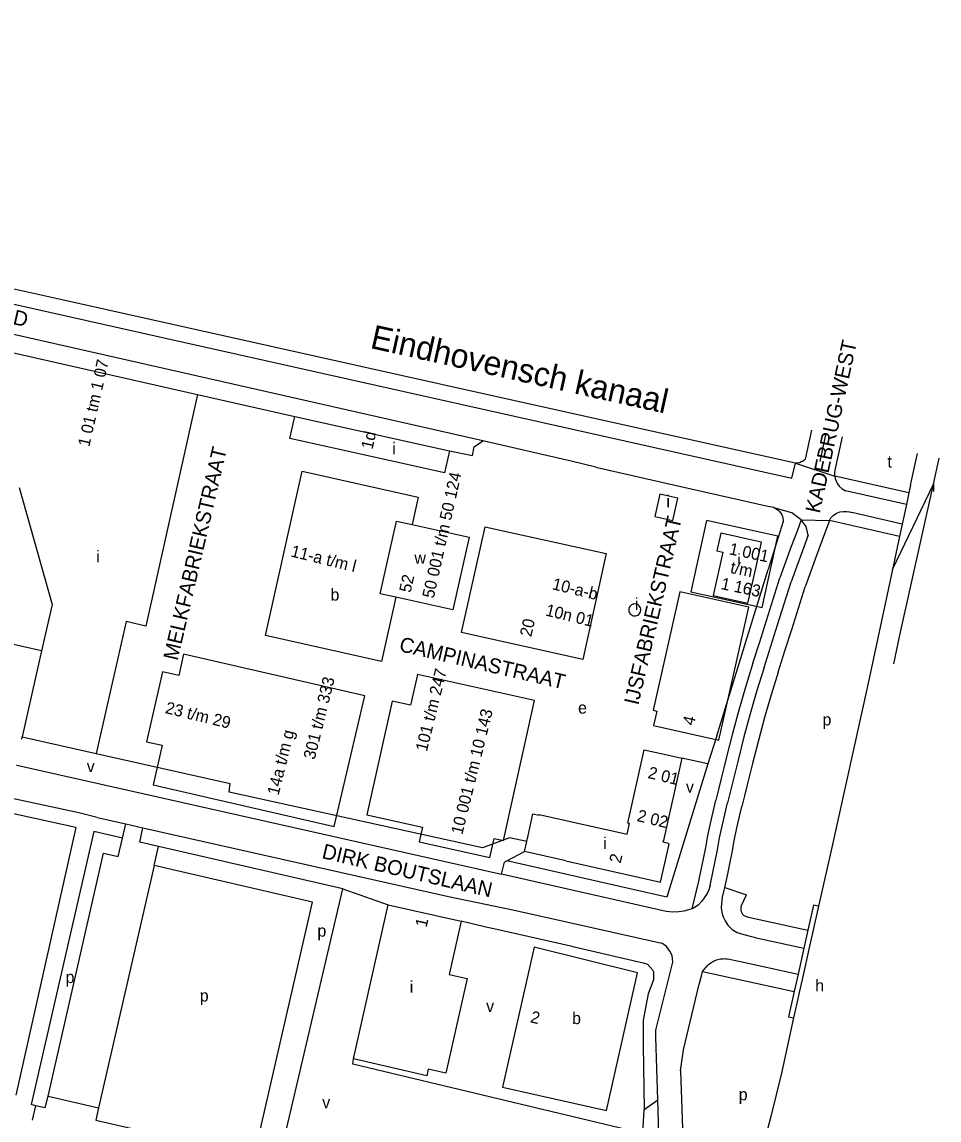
# Model space of a CAD drawing. Extents: x 161141 to 163125, y 381621 to 383200.
# Drawn here: x 162817.4 to 163125.3, y 382656.2 to 383024.9 of the extents above; entities that cross this region are included whole.
import ezdxf

# ---------------------------------------------------------------- set-up
doc = ezdxf.new("R2010")
doc.units = 0
for name, color, linetype in [('BLT_Basislijn', 7, 'Continuous'), ('BLT_Bebouwing', 7, 'Continuous'), ('BLT_Centroide', 7, 'Continuous'), ('BLT_Huisnummer', 7, 'Continuous'), ('BLT_Huisnummer_reeks', 7, 'Continuous'), ('BLT_Huisnummer_zonder_bebouwing', 7, 'Continuous'), ('BLT_Onderverdeling_panden', 7, 'Continuous'), ('BLT_Plantopo', 7, 'Continuous'), ('BLT_Straatnaam', 7, 'Continuous'), ('BLT_Vlakafsluiter', 7, 'Continuous'), ('BLT_Waternaam_spoorwegen', 7, 'Continuous')]:
    doc.layers.add(name, color=color, linetype=linetype)

msp = doc.modelspace()

# ---------------------------------------------------------------- linework, layer by layer
at = {"layer": 'BLT_Basislijn'}
for p, q in [((162831.37, 382931.53), (162791.15, 382940.41)), ((162971.77, 382900.12), (162831.37, 382931.53)), ((162972.07, 382884.19), (162784.79, 382926.71)), ((162876.34, 382899.77), (162908.95, 382892.43)), ((163077.05, 382876.8), (162971.77, 382900.12)), ((163082.42, 382887.86), (163080.31, 382878.14)), ((163087.27, 382886.78), (163085.22, 382877.29)), ((163001.72, 382877.46), (162972.07, 382884.19)), ((163092.78, 382885.56), (163090.34, 382874.35)), ((163115.73, 382869.33), (163118.05, 382879.97)), ((163010.09, 382875.43), (163001.72, 382877.46)), ((163010.09, 382875.43), (163038.54, 382868.93)), ((163038.54, 382868.93), (163067.84, 382862.25)), ((163115.73, 382869.33), (163115.18, 382866.78)), ((163115.18, 382866.78), (163114.34, 382862.87)), ((163075.85, 382860.07), (163070.28, 382861.67)), ((163114.34, 382862.87), (163112.91, 382856.23)), ((163072.95, 382857.14), (163067.87, 382841.07)), ((163078.96, 382857.69), (163075.85, 382860.07)), ((163112.91, 382856.23), (163112.03, 382852.15)), ((163112.03, 382852.15), (163109.64, 382841.01)), ((163050.62, 382785.2), (163067.87, 382841.07)), ((163050.62, 382785.2), (163047.7, 382775.74)), ((162842.29, 382779.29), (162887.32, 382769.12)), ((163047.7, 382775.74), (163038.87, 382777.68)), ((163047.7, 382775.74), (163033.88, 382731.03)), ((162835.43, 382754.42), (162811.5, 382759.61)), ((162842.6, 382757.8), (162852.24, 382755.63)), ((162835.43, 382754.42), (162815.29, 382664.48)), ((162851.15, 382750.81), (162852.24, 382755.63)), ((162852.24, 382755.63), (162858.02, 382754.33)), ((162856.91, 382749.49), (162858.02, 382754.33)), ((162858.02, 382754.33), (162960.64, 382731.22)), ((162841.5, 382753.01), (162820.49, 382661.34)), ((162851.15, 382750.81), (162841.5, 382753.01)), ((162863.21, 382748.04), (162856.91, 382749.49)), ((162861.74, 382741.6), (162863.21, 382748.04)), ((162925.07, 382733.82), (162863.21, 382748.04)), ((162980.18, 382743.23), (162986.11, 382746.32)), ((163023.43, 382733.4), (162980.18, 382743.23)), ((162861.74, 382741.6), (162843.07, 382660.22)), ((163033.62, 382726.22), (162978.42, 382738.71)), ((162903.62, 382641.96), (162925.07, 382733.82)), ((162925.07, 382733.82), (162940.34, 382728.46)), ((163033.88, 382731.03), (163023.43, 382733.4)), ((163053.36, 382734.24), (163060.58, 382731.82)), ((163058.82, 382727.99), (163060.58, 382731.82)), ((162973.15, 382720.97), (162964.85, 382722.96)), ((163061.26, 382724.33), (163081.27, 382719.88)), ((163063.46, 382717.46), (163079.92, 382713.85)), ((163081.27, 382719.88), (163079.92, 382713.85)), ((163082.93, 382719.51), (163081.58, 382713.49)), ((163082.94, 382719.51), (163082.85, 382719.13)), ((163079.92, 382713.85), (163077.96, 382705.11)), ((163081.58, 382713.49), (163079.61, 382704.75)), ((163045.9, 382706.06), (163076.65, 382699.31)), ((163058.66, 382709.36), (163077.96, 382705.11)), ((163077.96, 382705.11), (163076.65, 382699.31)), ((163079.61, 382704.75), (163078.3, 382698.95)), ((163030.89, 382662.95), (163030.24, 382683.96)), ((162928.46, 382674.89), (162928.66, 382676.65)), ((163025.81, 382651.58), (162928.46, 382674.89)), ((162825.22, 382660.21), (162826.13, 382664.2)), ((162826.13, 382664.2), (162843.07, 382660.22)), ((163026.23, 382659.74), (163030.89, 382662.95)), ((163031.38, 382647.3), (163030.89, 382662.95)), ((162822.05, 382660.97), (162820.49, 382661.34)), ((162820.88, 382656.11), (162822.05, 382660.97)), ((162825.22, 382660.21), (162822.05, 382660.97)), ((162843.07, 382660.22), (162842.14, 382656.15)), ((163025.81, 382651.58), (163026.23, 382659.74))]:
    msp.add_line(p, q, dxfattribs=at)
for points in [[(162389.3, 383024.91), (162483.39, 383004.41), (162704.86, 382954.77), (162862.06, 382919.53), (163075.83, 382871.69), (163077.05, 382876.8)], [(162960.92, 382880.88), (162968.64, 382879.34), (162969.22, 382882.25), (162972.07, 382884.19)], [(163080.31, 382878.14), (163079.9, 382877.69), (163079.45, 382877.36), (163079.01, 382877.14), (163078.39, 382876.91), (163077.78, 382876.8), (163077.05, 382876.8)], [(163123.4, 382869.7), (163125.27, 382878.37)], [(163090.34, 382874.35), (163090.22, 382873.54), (163090.22, 382872.55), (163090.26, 382872.36)], [(163115.18, 382866.78), (163090.26, 382872.36)], [(163090.26, 382872.36), (163090.4, 382871.62), (163090.75, 382870.7), (163091.21, 382869.77), (163091.79, 382869), (163092.71, 382868.16), (163093.88, 382867.48)], [(163110.05, 382809.31), (163112.09, 382818.95), (163123.4, 382869.7)], [(163114.34, 382862.87), (163093.88, 382867.48)], [(163067.84, 382862.25), (163068.47, 382862.22), (163069.1, 382862.12), (163069.7, 382861.93), (163070.28, 382861.67)], [(163070.28, 382861.67), (163070.82, 382861.34), (163071.31, 382860.94), (163071.75, 382860.49), (163072.13, 382859.98), (163072.44, 382859.43), (163072.68, 382858.84), (163072.85, 382858.23), (163072.93, 382857.61), (163072.95, 382857.14)], [(163078.96, 382857.69), (163077.59, 382853.94), (163075.68, 382848.72), (163073.77, 382843.49), (163071.85, 382838.27)], [(163081.35, 382852.57), (163080.68, 382855.45), (163078.96, 382857.69)], [(163088.46, 382857.47), (163086.07, 382850.93), (163084.16, 382845.7), (163082.24, 382840.48), (163080.33, 382835.25)], [(163088.46, 382857.47), (163088.96, 382858.34), (163089.74, 382859.22), (163090.87, 382859.96), (163092.04, 382860.4), (163093.17, 382860.5), (163094.28, 382860.53)], [(163112.03, 382852.15), (163088.46, 382857.47)], [(163094.28, 382860.53), (163095.21, 382860.39), (163095.97, 382860.23)], [(163112.91, 382856.23), (163095.97, 382860.23)], [(163081.09, 382851.86), (163081.35, 382852.57), (163079.44, 382847.34), (163077.52, 382842.12), (163075.61, 382836.89)], [(163109.64, 382841.01), (163101.42, 382802.87), (163089.01, 382746.64), (163084.83, 382727.95)], [(163062.81, 382809.63), (163065.07, 382816.79), (163067.33, 382823.95), (163069.59, 382831.11), (163071.85, 382838.27)], [(163066.51, 382808.08), (163068.77, 382815.24), (163071.03, 382822.4), (163073.29, 382829.56), (163075.61, 382836.89)], [(163071.28, 382806.61), (163073.55, 382813.77), (163075.81, 382820.93), (163078.07, 382828.09), (163080.33, 382835.25)], [(163062.81, 382809.63), (163060.32, 382801.57), (163058.06, 382793.77), (163055.93, 382785.93), (163053.93, 382778.12)], [(163066.51, 382808.08), (163064.13, 382800.36), (163061.89, 382792.62), (163059.77, 382784.85), (163057.79, 382777.06)], [(163071.28, 382806.61), (163068.94, 382798.97), (163066.72, 382791.31), (163064.62, 382783.61), (163062.64, 382775.86)], [(163053.93, 382778.12), (163053.01, 382774.42), (163052.12, 382770.82), (163051.23, 382767.21), (163050.35, 382763.61)], [(163057.79, 382777.06), (163056.9, 382773.46), (163056.01, 382769.86), (163055.12, 382766.26), (163054.22, 382762.64)], [(162815.54, 382775.38), (162815.7, 382775.34), (162978.42, 382738.71)], [(163062.64, 382775.86), (163061.76, 382772.28), (163060.87, 382768.68), (163059.98, 382765.08), (163059.09, 382761.48)], [(162986.85, 382749.65), (162981.03, 382750.9), (162972.05, 382747.51), (162886.94, 382766.3), (162887.32, 382769.12)], [(162842.6, 382757.8), (162836.52, 382759.3), (162812.56, 382764.5)], [(163046.95, 382747.73), (163047.7, 382751.7), (163048.52, 382755.7), (163049.41, 382759.69), (163050.35, 382763.61)], [(163050.87, 382746.94), (163051.61, 382750.87), (163052.42, 382754.81), (163053.3, 382758.74), (163054.22, 382762.64)], [(163055.78, 382746.01), (163056.52, 382749.91), (163057.31, 382753.77), (163058.17, 382757.62), (163059.09, 382761.48)], [(162826.13, 382664.2), (162844.81, 382745.75), (162849.74, 382744.6), (162851.15, 382750.81)], [(163042.41, 382727.12), (163044.63, 382736.41), (163045.45, 382740.14), (163046.22, 382743.88), (163046.95, 382747.73)], [(163048.4, 382734.99), (163048.52, 382735.51), (163049.36, 382739.3), (163050.15, 382743.11), (163050.87, 382746.94)], [(162978.42, 382738.71), (162979.37, 382742.8), (162980.18, 382743.23)], [(163053.36, 382734.24), (163054.25, 382738.26), (163055.05, 382742.14), (163055.78, 382746.01)], [(162895.29, 382643.91), (162914.89, 382729.3), (162861.74, 382741.6)], [(163048.4, 382734.99), (163047.98, 382733.44), (163047.4, 382732.24), (163046.46, 382730.72), (163045.64, 382729.65), (163044.36, 382728.34), (163042.84, 382727.27), (163042.41, 382727.12)], [(163052.48, 382730.56), (163053.36, 382734.24)], [(162960.64, 382731.22), (162982.18, 382726.71), (163032.22, 382715.59)], [(163052.48, 382730.56), (163052.21, 382728.86), (163052.11, 382727.44), (163052.31, 382725.86), (163052.82, 382724.44), (163053.48, 382723.02), (163054.4, 382721.64), (163055.82, 382720.17), (163057.55, 382719.15), (163059.73, 382718.44), (163062.36, 382717.78)], [(163084.83, 382727.95), (163083.17, 382728.33), (163081.27, 382719.88)], [(163042.41, 382727.12), (163040.87, 382726.61), (163039.55, 382726.28), (163037.95, 382726.03), (163035.93, 382725.91), (163033.62, 382726.22)], [(163058.82, 382727.99), (163058.71, 382727.53), (163058.68, 382727.06), (163058.73, 382726.59), (163058.86, 382726.14), (163059.06, 382725.71), (163059.33, 382725.32), (163059.66, 382724.99), (163060.04, 382724.71), (163060.47, 382724.51), (163060.92, 382724.38), (163061.26, 382724.33)], [(163084.83, 382727.95), (163082.93, 382719.51)], [(163002.08, 382714.46), (162975.77, 382720.34), (162973.15, 382720.97)], [(163062.36, 382717.78), (163063.2, 382717.52), (163063.46, 382717.46)], [(163002.08, 382714.46), (163002.33, 382714.4), (163025.97, 382708.95), (163027.41, 382708.48), (163029.06, 382706.63), (163029.38, 382705.94), (163029.42, 382703.24), (163027.6, 382698.55), (163025.95, 382689.74)], [(163030.23, 382686.33), (163035.88, 382709.2), (163035.68, 382711.39), (163034.89, 382712.82), (163033.74, 382714.46), (163032.22, 382715.59)], [(163045.9, 382706.06), (163046.98, 382707.34), (163047.27, 382707.68), (163047.56, 382708.03), (163047.89, 382708.35), (163048.22, 382708.66), (163048.6, 382708.93), (163048.99, 382709.19), (163049.4, 382709.42), (163049.81, 382709.64), (163050.58, 382709.96), (163051, 382710.09), (163051.42, 382710.23), (163051.86, 382710.28), (163052.76, 382710.34), (163053.22, 382710.36), (163053.7, 382710.34), (163054.17, 382710.33), (163054.93, 382710.2), (163055.95, 382709.98), (163056.96, 382709.75), (163058.66, 382709.36)], [(163038.49, 382672.64), (163039.48, 382679.71), (163044.67, 382701.28), (163045.07, 382702.93), (163045.47, 382704.59), (163045.9, 382706.06)], [(163076.65, 382699.31), (163074.69, 382690.83), (163076.43, 382690.46)], [(163078.3, 382698.95), (163077.51, 382695.44), (163076.43, 382690.46)], [(163025.95, 382689.74), (163025.9, 382681.23), (163026.23, 382659.74)], [(163076.43, 382690.46), (163072.41, 382671.94)], [(163030.24, 382683.96), (163030.22, 382685.97), (163030.23, 382686.33)], [(163038.49, 382672.64), (163042.63, 382553.68), (163042.99, 382553.68)], [(163072.41, 382671.94), (163070.64, 382664.62), (163068.78, 382657.31), (163066.85, 382650.03), (163064.84, 382642.76), (163062.75, 382635.52), (163060.59, 382628.3), (163059.84, 382625.87)], [(162842.14, 382656.15), (162895.29, 382643.91)]]:
    msp.add_lwpolyline(points, dxfattribs=at)
at = {"layer": 'BLT_Bebouwing'}
for p, q in [((162803.35, 382916.37), (162875.31, 382900)), ((162875.31, 382900), (162876.34, 382899.77)), ((162959.29, 382873.53), (162935.63, 382878.78)), ((163035.9, 382857.53), (163037.57, 382865.03)), ((162817.35, 382784.05), (162817.44, 382784.8)), ((162817.44, 382784.8), (162842.29, 382779.29)), ((163038.87, 382777.68), (163032.76, 382750)), ((162986.11, 382746.32), (162986.85, 382749.65)), ((163000, 382743.15), (162986.11, 382746.32)), ((163000, 382743.15), (163024.4, 382737.69)), ((162928.66, 382676.65), (162940.34, 382728.46)), ((162940.34, 382728.46), (162964.85, 382722.96))]:
    msp.add_line(p, q, dxfattribs=at)
for points in [[(162876.34, 382899.77), (162858.93, 382822.03), (162852.35, 382823.53), (162842.29, 382779.29)], [(162935.63, 382878.78), (162907.31, 382885.07), (162908.95, 382892.43)], [(162908.95, 382892.43), (162960.92, 382880.88)], [(162960.92, 382880.88), (162959.29, 382873.53)], [(162942.92, 382831.74), (162938.12, 382810.16), (162899.16, 382818.83), (162911.46, 382874.03), (162950.39, 382865.38), (162948.34, 382856.13)], [(162816.47, 382868.55), (162827.54, 382829.33), (162824, 382813.68)], [(163037.57, 382865.03), (163031.57, 382866.37), (163029.9, 382858.86), (163035.9, 382857.53)], [(162948.34, 382856.13), (162967.5, 382851.86), (162962.08, 382827.47), (162942.92, 382831.74)], [(163063.83, 382841.9), (163065.68, 382850.23), (163059.98, 382851.5), (163057.12, 382852.14), (163052.02, 382853.28), (163050.69, 382847.34), (163052.65, 382846.9)], [(163052.65, 382846.9), (163049.4, 382832.31), (163061.11, 382829.7), (163063.83, 382841.9)], [(163021.36, 382826.49), (163021.59, 382826.16), (163021.87, 382825.88), (163022.21, 382825.66), (163022.58, 382825.51), (163022.98, 382825.44), (163023.38, 382825.45), (163023.77, 382825.54), (163024.14, 382825.7), (163024.47, 382825.93), (163024.74, 382826.22), (163024.95, 382826.57), (163025.09, 382826.94), (163025.16, 382827.34), (163025.14, 382827.74), (163025.04, 382828.13), (163024.87, 382828.49), (163024.63, 382828.82), (163024.34, 382829.08), (163023.99, 382829.29), (163023.61, 382829.42), (163023.21, 382829.48), (163022.81, 382829.45), (163022.42, 382829.35), (163022.06, 382829.17), (163021.75, 382828.92), (163021.48, 382828.62), (163021.29, 382828.27), (163021.16, 382827.88), (163021.12, 382827.49), (163021.15, 382827.09), (163021.26, 382826.7), (163021.36, 382826.49)], [(162824, 382813.68), (162810, 382816.85), (162804.38, 382792.13), (162803.27, 382787.25)], [(162986.85, 382749.65), (162986.93, 382750), (162987.19, 382751.2), (162988.95, 382758.93), (162990.98, 382758.48), (162991.04, 382758.73), (163000, 382756.73), (163020.57, 382752.15), (163021.36, 382755.71), (163020.81, 382755.84), (163026.31, 382780.48), (163033.99, 382778.77), (163038.87, 382777.68)], [(163024.4, 382737.69), (163031.74, 382736.04), (163034.62, 382748.84), (163034.46, 382748.88), (163034.49, 382749.02), (163032.63, 382749.43), (163032.76, 382750)], [(162964.85, 382722.96), (162960.8, 382704.99), (162966.82, 382703.64), (162965.72, 382698.76), (162959.67, 382671.92), (162953.78, 382673.25), (162953.27, 382670.98), (162928.66, 382676.65)]]:
    msp.add_lwpolyline(points, dxfattribs=at)
msp.add_lwpolyline([(162989.3, 382714.26), (162978.75, 382667.14), (163013.67, 382659.35), (163024.01, 382705.64)], close=True, dxfattribs=at)
at = {"layer": 'BLT_Onderverdeling_panden'}
msp.add_line((162824, 382813.68), (162817.44, 382784.8), dxfattribs=at)
msp.add_lwpolyline([(162942.92, 382831.74), (162937.67, 382832.9), (162943.08, 382857.3), (162948.34, 382856.13)], dxfattribs=at)
at = {"layer": 'BLT_Plantopo'}
for points in [[(163047.19, 382857.5), (163041.89, 382833.55), (163065.84, 382828.26), (163071.14, 382852.2)], [(162972.84, 382855.41), (162975.41, 382854.84), (163013.55, 382846.36), (163005.65, 382810.8), (162964.94, 382819.84)], [(163038.25, 382833.59), (163029.25, 382793.75), (163030.5, 382793.47), (163029.4, 382788.61), (163051.33, 382783.67), (163061.42, 382828.37)], [(162871.64, 382812.59), (162870.01, 382805.47), (162864.54, 382806.72), (162859.22, 382783.19), (162864.45, 382781.99), (162861.4, 382768.67), (162922.15, 382754.76), (162932.51, 382798.65)]]:
    msp.add_lwpolyline(points, close=True, dxfattribs=at)
msp.add_lwpolyline([(162950.15, 382805.76), (162947.87, 382795.49), (162941.63, 382796.87), (162933.15, 382758.61), (162951.81, 382754.48), (162950.72, 382749.58), (162974.49, 382744.31), (162975.9, 382750.69), (162979.04, 382749.99), (162989.45, 382797.05), (162950.15, 382805.76)], dxfattribs=at)
at = {"layer": 'BLT_Vlakafsluiter'}
for p, q in [((163077.05, 382876.8), (163090.26, 382872.36)), ((163109.64, 382841.01), (163123.4, 382869.7)), ((163123.4, 382869.7), (163123.37, 382867.27)), ((163078.96, 382857.69), (163088.46, 382857.47))]:
    msp.add_line(p, q, dxfattribs=at)

# ---------------------------------------------------------------- texts
at = {"layer": 'BLT_Centroide'}
for s, p in [('i', (162941.71, 382879.71)), ('t', (163107.96, 382875.26)), ('i', (163033.73, 382861.94)), ('i', (162842.33, 382843.42)), ('i', (163057.55, 382842.27)), ('w', (162949.15, 382842.95)), ('b', (162920.97, 382830.6)), ('i', (163023.14, 382827.47)), ('e', (163004.08, 382792.64)), ('p', (163086.14, 382788.67)), ('v', (162839.14, 382773)), ('v', (163040.3, 382766.08)), ('i', (163012.5, 382747.14)), ('p', (162916.58, 382717.74)), ('p', (162832.03, 382702.16)), ('i', (162947.56, 382698.89)), ('h', (163083.69, 382699.33)), ('p', (162877.08, 382695.95)), ('v', (162973.23, 382692.46)), ('b', (163002.08, 382688.36)), ('p', (163058.02, 382662.78)), ('v', (162918.19, 382660.1))]:
    msp.add_text(s, height=4, dxfattribs=at).set_placement(p)
at = {"layer": 'BLT_Huisnummer'}
for s, rotation, p in [('1d', 77.1859, (162935.05, 382881.15)), ('1', 77.4835, (162953.22, 382720.65)), ('2', 346.1901, (162987.82, 382689.03))]:
    msp.add_text(s, height=4, rotation=rotation, dxfattribs=at).set_placement(p)
at = {"layer": 'BLT_Huisnummer_reeks'}
for s, rotation, p in [('1 01 tm 1 07', 77.1859, (162839.98, 382882.05)), ('50 001 t/m 50 124', 77.4835, (162955.62, 382831.14)), ('11-a t/m l', 346.1901, (162907.39, 382845.45)), ('52', 77.4835, (162947.86, 382833.03)), ('2 01', 346.1901, (163027.27, 382771.07)), ('2 02', 346.1901, (163023.62, 382756.62)), ('2', 77.3092, (163018.37, 382742.19))]:
    msp.add_text(s, height=4, rotation=rotation, dxfattribs=at).set_placement(p)
at = {"layer": 'BLT_Huisnummer_zonder_bebouwing'}
for s, rotation, p in [('1 001', 348.1901, (163054.57, 382846.17)), ('t/m', 348.1901, (163054.97, 382839.96)), ('10-a-b', 346.1901, (162995.15, 382834.44)), ('1 163', 348.1901, (163051.8, 382834.49)), ('10n 01', 346.1901, (162992.9, 382825.64)), ('20', 77.4835, (162988.36, 382818.21)), ('101 t/m 247', 76.1901, (162953.32, 382779.7)), ('301 t/m 333', 76.1901, (162915.68, 382776.98)), ('23 t/m 29', 346.1901, (162865.25, 382792.86)), ('10 001 t/m 10 143', 76.1901, (162965.21, 382751.77)), ('4', 76.1901, (163042.94, 382788.44)), ('14a t/m g', 76.1901, (162903.53, 382764.99))]:
    msp.add_text(s, height=4, rotation=rotation, dxfattribs=at).set_placement(p)
at = {"layer": 'BLT_Straatnaam'}
for s, rotation, p in [('KANAALDIJK-ZUID', 347.0644, (162761.58, 382935.54)), ('KADEBRUG-WEST', 77.7596, (163085.2, 382859.69)), ('MELKFABRIEKSTRAAT', 76.8771, (162869.64, 382810.23)), ('IJSFABRIEKSTRAAT', 76.8771, (163024.29, 382795.26)), ('CAMPINASTRAAT', 346.8771, (162943.76, 382813.67)), ('DIRK BOUTSLAAN', 346.8771, (162917.81, 382744.14))]:
    msp.add_text(s, height=5, rotation=rotation, dxfattribs=at).set_placement(p)
at = {"layer": 'BLT_Waternaam_spoorwegen'}
msp.add_text('Eindhovensch kanaal', height=8, rotation=347.4736, dxfattribs=at).set_placement((162933.99, 382915.46))

doc.saveas('drawing.dxf')
